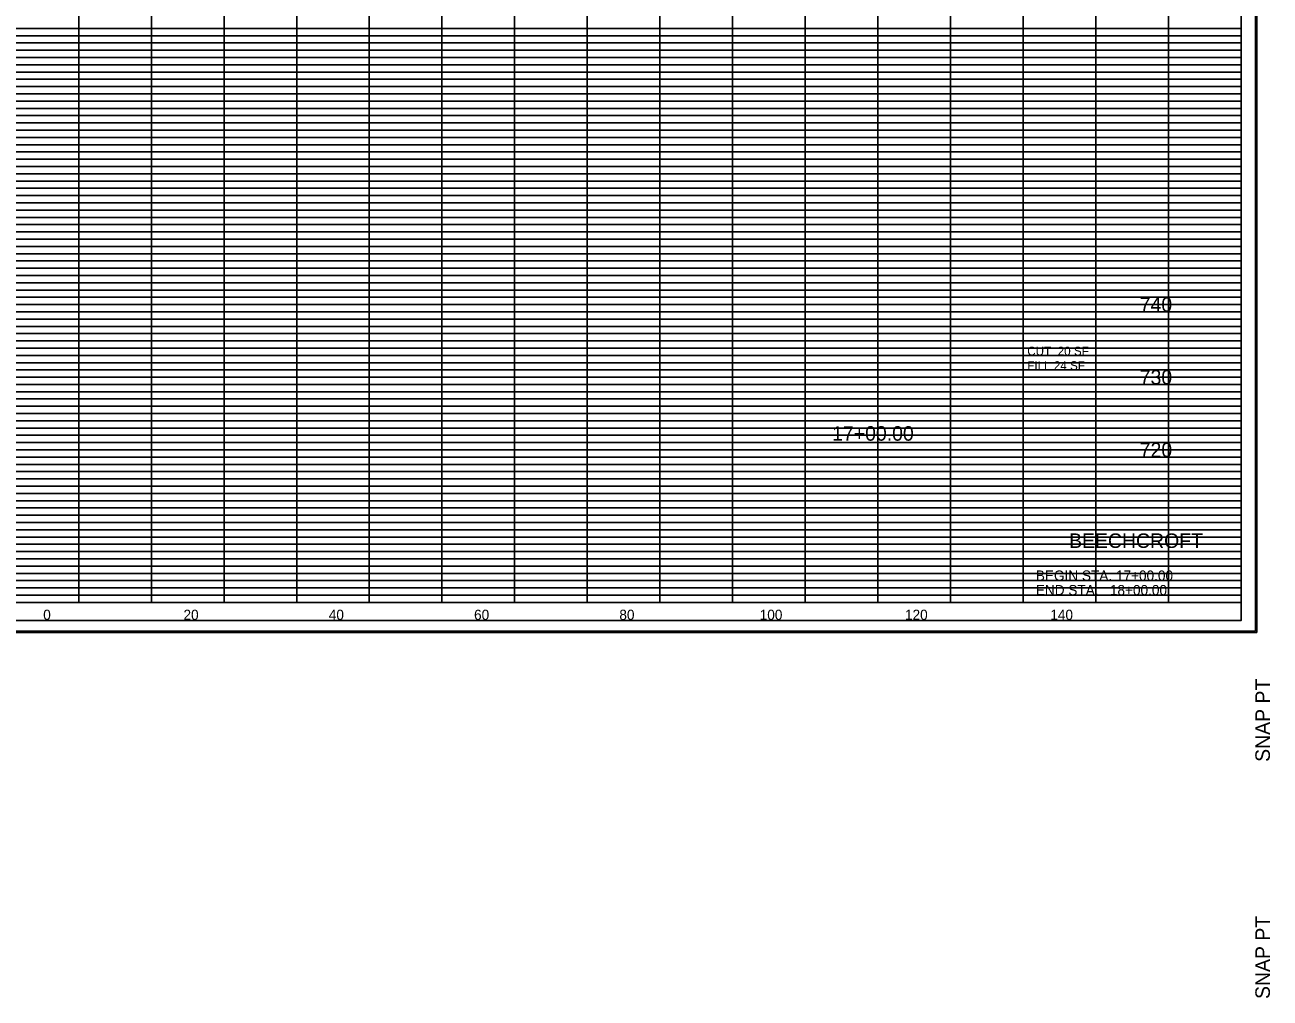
# Model space of a CAD drawing. Extents: x -200 to 1704, y -325 to 2307.
# Drawn here: x 1152.6 to 1324, y 1755.5 to 1889.5 of the extents above; entities that cross this region are included whole.
import ezdxf

# ---------------------------------------------------------------- set-up
doc = ezdxf.new("R2010")
doc.units = 0
for name, color, linetype in [('DESIGN - SHEET - Corner Text', 7, 'Continuous'), ('DESIGN - SHEET - Light Grid', 7, 'Continuous'), ('DESIGN - SHEET - Linework', 7, 'Continuous'), ('DESIGN - SHEET - Plot Shape', 7, 'Continuous'), ('DESIGN - TYPICAL - Text', 7, 'Continuous')]:
    doc.layers.add(name, color=color, linetype=linetype)

msp = doc.modelspace()

# ---------------------------------------------------------------- linework, layer by layer
at = {"layer": 'DESIGN - SHEET - Light Grid'}
for p, q in [((1080, 1889), (1160, 1889)), ((1160, 1889), (1240, 1889)), ((1240, 1889), (1320, 1889)), ((1080, 1888), (1160, 1888)), ((1160, 1888), (1240, 1888)), ((1240, 1888), (1320, 1888)), ((1080, 1887), (1160, 1887)), ((1080, 1886), (1160, 1886)), ((1160, 1887), (1240, 1887)), ((1160, 1886), (1240, 1886)), ((1240, 1887), (1320, 1887)), ((1240, 1886), (1320, 1886)), ((1080, 1885), (1160, 1885)), ((1080, 1884), (1160, 1884)), ((1160, 1885), (1240, 1885)), ((1160, 1884), (1240, 1884)), ((1240, 1885), (1320, 1885)), ((1240, 1884), (1320, 1884)), ((1080, 1883), (1160, 1883)), ((1160, 1883), (1240, 1883)), ((1240, 1883), (1320, 1883)), ((1080, 1882), (1160, 1882)), ((1080, 1881), (1160, 1881)), ((1160, 1882), (1240, 1882)), ((1160, 1881), (1240, 1881)), ((1240, 1882), (1320, 1882)), ((1240, 1881), (1320, 1881)), ((1080, 1879), (1160, 1879)), ((1160, 1879), (1240, 1879)), ((1240, 1879), (1320, 1879)), ((1080, 1878), (1160, 1878)), ((1080, 1877), (1160, 1877)), ((1160, 1878), (1240, 1878)), ((1160, 1877), (1240, 1877)), ((1240, 1878), (1320, 1878)), ((1240, 1877), (1320, 1877)), ((1080, 1876), (1160, 1876)), ((1160, 1876), (1240, 1876)), ((1240, 1876), (1320, 1876)), ((1080, 1875), (1160, 1875)), ((1080, 1874), (1160, 1874)), ((1160, 1875), (1240, 1875)), ((1160, 1874), (1240, 1874)), ((1240, 1875), (1320, 1875)), ((1240, 1874), (1320, 1874)), ((1080, 1873), (1160, 1873)), ((1080, 1872), (1160, 1872)), ((1160, 1873), (1240, 1873)), ((1160, 1872), (1240, 1872)), ((1240, 1873), (1320, 1873)), ((1240, 1872), (1320, 1872)), ((1080, 1871), (1160, 1871)), ((1160, 1871), (1240, 1871)), ((1240, 1871), (1320, 1871)), ((1080, 1869), (1160, 1869)), ((1160, 1869), (1240, 1869)), ((1240, 1869), (1320, 1869)), ((1080, 1868), (1160, 1868)), ((1080, 1867), (1160, 1867)), ((1160, 1868), (1240, 1868)), ((1160, 1867), (1240, 1867)), ((1240, 1868), (1320, 1868)), ((1240, 1867), (1320, 1867)), ((1080, 1866), (1160, 1866)), ((1080, 1865), (1160, 1865)), ((1160, 1866), (1240, 1866)), ((1160, 1865), (1240, 1865)), ((1240, 1866), (1320, 1866)), ((1240, 1865), (1320, 1865)), ((1080, 1864), (1160, 1864)), ((1160, 1864), (1240, 1864)), ((1240, 1864), (1320, 1864)), ((1080, 1863), (1160, 1863)), ((1080, 1862), (1160, 1862)), ((1160, 1863), (1240, 1863)), ((1160, 1862), (1240, 1862)), ((1240, 1863), (1320, 1863)), ((1240, 1862), (1320, 1862)), ((1080, 1861), (1160, 1861)), ((1160, 1861), (1240, 1861)), ((1240, 1861), (1320, 1861)), ((1080, 1859), (1160, 1859)), ((1160, 1859), (1240, 1859)), ((1240, 1859), (1320, 1859)), ((1080, 1858), (1160, 1858)), ((1080, 1857), (1160, 1857)), ((1160, 1858), (1240, 1858)), ((1160, 1857), (1240, 1857)), ((1240, 1858), (1320, 1858)), ((1240, 1857), (1320, 1857)), ((1080, 1856), (1160, 1856)), ((1080, 1855), (1160, 1855)), ((1160, 1856), (1240, 1856)), ((1160, 1855), (1240, 1855)), ((1240, 1856), (1320, 1856)), ((1240, 1855), (1320, 1855)), ((1080, 1854), (1160, 1854)), ((1080, 1853), (1160, 1853)), ((1160, 1854), (1240, 1854)), ((1160, 1853), (1240, 1853)), ((1240, 1854), (1320, 1854)), ((1240, 1853), (1320, 1853)), ((1080, 1852), (1160, 1852)), ((1160, 1852), (1240, 1852)), ((1240, 1852), (1320, 1852)), ((1080, 1851), (1160, 1851)), ((1160, 1851), (1240, 1851)), ((1240, 1851), (1320, 1851)), ((1080, 1849), (1160, 1849)), ((1080, 1848), (1160, 1848)), ((1160, 1849), (1240, 1849)), ((1160, 1848), (1240, 1848)), ((1240, 1849), (1320, 1849)), ((1240, 1848), (1320, 1848)), ((1080, 1847), (1160, 1847)), ((1160, 1847), (1240, 1847)), ((1240, 1847), (1320, 1847)), ((1080, 1846), (1160, 1846)), ((1080, 1845), (1160, 1845)), ((1160, 1846), (1240, 1846)), ((1160, 1845), (1240, 1845)), ((1240, 1846), (1320, 1846)), ((1240, 1845), (1320, 1845)), ((1080, 1844), (1160, 1844)), ((1080, 1843), (1160, 1843)), ((1160, 1844), (1240, 1844)), ((1160, 1843), (1240, 1843)), ((1240, 1844), (1320, 1844)), ((1240, 1843), (1320, 1843)), ((1080, 1842), (1160, 1842)), ((1080, 1841), (1160, 1841)), ((1160, 1842), (1240, 1842)), ((1160, 1841), (1240, 1841)), ((1240, 1842), (1320, 1842)), ((1240, 1841), (1320, 1841)), ((1080, 1839), (1160, 1839)), ((1080, 1838), (1160, 1838)), ((1160, 1839), (1240, 1839)), ((1160, 1838), (1240, 1838)), ((1240, 1839), (1320, 1839)), ((1240, 1838), (1320, 1838)), ((1080, 1837), (1160, 1837)), ((1080, 1836), (1160, 1836)), ((1160, 1837), (1240, 1837)), ((1160, 1836), (1240, 1836)), ((1240, 1837), (1320, 1837)), ((1240, 1836), (1320, 1836)), ((1080, 1835), (1160, 1835)), ((1160, 1835), (1240, 1835)), ((1240, 1835), (1320, 1835)), ((1080, 1834), (1160, 1834)), ((1080, 1833), (1160, 1833)), ((1160, 1834), (1240, 1834)), ((1160, 1833), (1240, 1833)), ((1240, 1834), (1320, 1834)), ((1240, 1833), (1320, 1833)), ((1080, 1832), (1160, 1832)), ((1080, 1831), (1160, 1831)), ((1160, 1832), (1240, 1832)), ((1160, 1831), (1240, 1831)), ((1240, 1832), (1320, 1832)), ((1240, 1831), (1320, 1831)), ((1080, 1829), (1160, 1829)), ((1160, 1829), (1240, 1829)), ((1240, 1829), (1320, 1829)), ((1080, 1828), (1160, 1828)), ((1160, 1828), (1240, 1828)), ((1240, 1828), (1320, 1828)), ((1080, 1827), (1160, 1827)), ((1080, 1826), (1160, 1826)), ((1160, 1827), (1240, 1827)), ((1160, 1826), (1240, 1826)), ((1240, 1827), (1320, 1827)), ((1240, 1826), (1320, 1826)), ((1080, 1825), (1160, 1825)), ((1080, 1824), (1160, 1824)), ((1160, 1825), (1240, 1825)), ((1160, 1824), (1240, 1824)), ((1240, 1825), (1320, 1825)), ((1240, 1824), (1320, 1824)), ((1080, 1823), (1160, 1823)), ((1160, 1823), (1240, 1823)), ((1240, 1823), (1320, 1823)), ((1080, 1822), (1160, 1822)), ((1080, 1821), (1160, 1821)), ((1160, 1822), (1240, 1822)), ((1160, 1821), (1240, 1821)), ((1240, 1822), (1320, 1822)), ((1240, 1821), (1320, 1821)), ((1080, 1819), (1160, 1819)), ((1160, 1819), (1240, 1819)), ((1240, 1819), (1320, 1819)), ((1080, 1818), (1160, 1818)), ((1080, 1817), (1160, 1817)), ((1160, 1818), (1240, 1818)), ((1160, 1817), (1240, 1817)), ((1240, 1818), (1320, 1818)), ((1240, 1817), (1320, 1817)), ((1080, 1816), (1160, 1816)), ((1160, 1816), (1240, 1816)), ((1240, 1816), (1320, 1816)), ((1080, 1815), (1160, 1815)), ((1080, 1814), (1160, 1814)), ((1160, 1815), (1240, 1815)), ((1160, 1814), (1240, 1814)), ((1240, 1815), (1320, 1815)), ((1240, 1814), (1320, 1814)), ((1080, 1813), (1160, 1813)), ((1080, 1812), (1160, 1812)), ((1160, 1813), (1240, 1813)), ((1160, 1812), (1240, 1812)), ((1240, 1813), (1320, 1813)), ((1240, 1812), (1320, 1812)), ((1080, 1811), (1160, 1811)), ((1160, 1811), (1240, 1811)), ((1240, 1811), (1320, 1811))]:
    msp.add_line(p, q, dxfattribs=at)
at = {"layer": 'DESIGN - SHEET - Linework'}
for p, q in [((1322.17, 2024.14), (1322.17, 1805.86)), ((1160, 1810), (1160, 2020)), ((1170, 1810), (1170, 2020)), ((1180, 1810), (1180, 2020)), ((1190, 1810), (1190, 2020)), ((1200, 1810), (1200, 2020)), ((1210, 1810), (1210, 2020)), ((1220, 1810), (1220, 2020)), ((1230, 1810), (1230, 2020)), ((1240, 1810), (1240, 2020)), ((1250, 1810), (1250, 2020)), ((1260, 1810), (1260, 2020)), ((1270, 1810), (1270, 2020)), ((1280, 1810), (1280, 2010)), ((1290, 1810), (1290, 2010)), ((1300, 1810), (1300, 2010)), ((1310, 1810), (1310, 2010)), ((1000, 1880), (1320, 1880)), ((1000, 1870), (1320, 1870)), ((1000, 1860), (1320, 1860)), ((1000, 1850), (1320, 1850)), ((1000, 1840), (1320, 1840)), ((1000, 1830), (1320, 1830)), ((1000, 1820), (1320, 1820)), ((981.77, 1805.86), (1322.17, 1805.86))]:
    msp.add_line(p, q, dxfattribs=at)
msp.add_lwpolyline([(1000, 2020), (1000, 1810), (1320, 1810), (1320, 2020), (1000, 2020)], dxfattribs=at)
at = {"layer": 'DESIGN - SHEET - Plot Shape'}
for points in [[(981.97, 2023.94), (1321.97, 2023.94), (1321.97, 1806.06), (981.97, 1806.06)], [(991.5, 2020), (1320, 2020), (1320, 1807.5), (991.5, 1807.5)]]:
    msp.add_lwpolyline(points, close=True, dxfattribs=at)

# ---------------------------------------------------------------- texts
at = {"layer": 'DESIGN - SHEET - Corner Text'}
for s, height, p in [('BEECHCROFT ', 2, (1296.33, 1817.5)), ('BEGIN STA. 17+00.00', 1.4, (1291.75, 1813)), ('END STA.   18+00.00', 1.4, (1291.75, 1811))]:
    msp.add_text(s, height=height, dxfattribs=at).set_placement(p)
for s, p in [('SNAP PT  ', (1323.97, 1788.06)), ('  SNAP PT', (1323.97, 1753.94))]:
    msp.add_text(s, height=2, rotation=90, dxfattribs=at).set_placement(p)
at = {"layer": 'DESIGN - TYPICAL - Text'}
for s, height, p in [('     740     ', 2, (1302.34, 1850)), ('CUT  20 SF', 1.2, (1290.57, 1844)), ('FILL 24 SF', 1.2, (1290.57, 1842)), ('     730     ', 2, (1302.34, 1840)), ('     17+00.00     ', 2, (1260, 1832.26)), ('     720     ', 2, (1302.34, 1830)), ('     0     ', 1.4, (1152.51, 1807.6)), ('     20     ', 1.4, (1171.82, 1807.6)), ('     40     ', 1.4, (1191.82, 1807.6)), ('     60     ', 1.4, (1211.82, 1807.6)), ('     80     ', 1.4, (1231.82, 1807.6)), ('     100     ', 1.4, (1251.14, 1807.6)), ('     120     ', 1.4, (1271.14, 1807.6)), ('     140     ', 1.4, (1291.14, 1807.6))]:
    msp.add_text(s, height=height, dxfattribs=at).set_placement(p)

doc.saveas('drawing.dxf')
